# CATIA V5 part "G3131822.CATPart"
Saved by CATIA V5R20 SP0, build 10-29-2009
Part number: G3131822
Revision: 8
Definition: design
Nomenclature: G3131822
Source: made
Description: NOT SPECIFIED
Bounding box of the stored display mesh (mm): x -17 to 22, y -15.5 to 15.5, z -15.5 to 15.5
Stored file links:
  C:\Users\Raffaele\Desktop\3D X SITO CF\BOLEX\24-BUSH REF 313\G3131822.CATPart
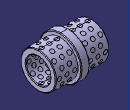
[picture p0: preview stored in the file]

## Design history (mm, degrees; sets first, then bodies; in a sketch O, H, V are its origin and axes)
Body1 "MANIFOLD_SOLID_BREP #11295" (main body)
  Solid1: solid without history
Body2 "MANIFOLD_SOLID_BREP #11438"
  Solid2: solid without history
Body3 "MANIFOLD_SOLID_BREP #11581"
  Solid3: solid without history
Body4 "MANIFOLD_SOLID_BREP #11724"
  Solid4: solid without history
Body5 "MANIFOLD_SOLID_BREP #11867"
  Solid5: solid without history
Body6 "MANIFOLD_SOLID_BREP #12012"
  Solid6: solid without history
Body7 "MANIFOLD_SOLID_BREP #12157"
  Solid7: solid without history
Body8 "MANIFOLD_SOLID_BREP #12302"
  Solid8: solid without history
Body9 "MANIFOLD_SOLID_BREP #12447"
  Solid9: solid without history
Body10 "MANIFOLD_SOLID_BREP #12592"
  Solid10: solid without history
Body11 "MANIFOLD_SOLID_BREP #12737"
  Solid11: solid without history
Body12 "MANIFOLD_SOLID_BREP #12882"
  Solid12: solid without history
Body13 "MANIFOLD_SOLID_BREP #13027"
  Solid13: solid without history
Body14 "MANIFOLD_SOLID_BREP #13172"
  Solid14: solid without history
Body15 "MANIFOLD_SOLID_BREP #13317"
  Solid15: solid without history
Body16 "MANIFOLD_SOLID_BREP #13462"
  Solid16: solid without history
Body17 "MANIFOLD_SOLID_BREP #13607"
  Solid17: solid without history
Body18 "MANIFOLD_SOLID_BREP #13754"
  Solid18: solid without history
Body19 "MANIFOLD_SOLID_BREP #13901"
  Solid19: solid without history
Body20 "MANIFOLD_SOLID_BREP #14048"
  Solid20: solid without history
Body21 "MANIFOLD_SOLID_BREP #14195"
  Solid21: solid without history
Body22 "MANIFOLD_SOLID_BREP #14340"
  Solid22: solid without history
Body23 "MANIFOLD_SOLID_BREP #14487"
  Solid23: solid without history
Body24 "MANIFOLD_SOLID_BREP #14634"
  Solid24: solid without history
Body25 "MANIFOLD_SOLID_BREP #14779"
  Solid25: solid without history
Body26 "MANIFOLD_SOLID_BREP #14924"
  Solid26: solid without history
Body27 "MANIFOLD_SOLID_BREP #15069"
  Solid27: solid without history
Body28 "MANIFOLD_SOLID_BREP #15214"
  Solid28: solid without history
Body29 "MANIFOLD_SOLID_BREP #15359"
  Solid29: solid without history
Body30 "MANIFOLD_SOLID_BREP #15504"
  Solid30: solid without history
Body31 "MANIFOLD_SOLID_BREP #15649"
  Solid31: solid without history
Body32 "MANIFOLD_SOLID_BREP #15792"
  Solid32: solid without history
Body33 "MANIFOLD_SOLID_BREP #15935"
  Solid33: solid without history
Body34 "MANIFOLD_SOLID_BREP #16082"
  Solid34: solid without history
Body35 "MANIFOLD_SOLID_BREP #16229"
  Solid35: solid without history
Body36 "MANIFOLD_SOLID_BREP #16376"
  Solid36: solid without history
Body37 "MANIFOLD_SOLID_BREP #16523"
  Solid37: solid without history
Body38 "MANIFOLD_SOLID_BREP #16668"
  Solid38: solid without history
Body39 "MANIFOLD_SOLID_BREP #16815"
  Solid39: solid without history
Body40 "MANIFOLD_SOLID_BREP #16962"
  Solid40: solid without history
Body41 "MANIFOLD_SOLID_BREP #17107"
  Solid41: solid without history
Body42 "MANIFOLD_SOLID_BREP #17252"
  Solid42: solid without history
Body43 "MANIFOLD_SOLID_BREP #17397"
  Solid43: solid without history
Body44 "MANIFOLD_SOLID_BREP #17542"
  Solid44: solid without history
Body45 "MANIFOLD_SOLID_BREP #17687"
  Solid45: solid without history
Body46 "MANIFOLD_SOLID_BREP #17832"
  Solid46: solid without history
Body47 "MANIFOLD_SOLID_BREP #17977"
  Solid47: solid without history
Body48 "MANIFOLD_SOLID_BREP #18122"
  Solid48: solid without history
Body49 "MANIFOLD_SOLID_BREP #18267"
  Solid49: solid without history
Body50 "MANIFOLD_SOLID_BREP #18412"
  Solid50: solid without history
Body51 "MANIFOLD_SOLID_BREP #18557"
  Solid51: solid without history
Body52 "MANIFOLD_SOLID_BREP #18702"
  Solid52: solid without history
Body53 "MANIFOLD_SOLID_BREP #18847"
  Solid53: solid without history
Body54 "MANIFOLD_SOLID_BREP #18992"
  Solid54: solid without history
Body55 "MANIFOLD_SOLID_BREP #19137"
  Solid55: solid without history
Body56 "MANIFOLD_SOLID_BREP #19282"
  Solid56: solid without history
Body57 "MANIFOLD_SOLID_BREP #19427"
  Solid57: solid without history
Body58 "MANIFOLD_SOLID_BREP #19572"
  Solid58: solid without history
Body59 "MANIFOLD_SOLID_BREP #19717"
  Solid59: solid without history
Body60 "MANIFOLD_SOLID_BREP #19860"
  Solid60: solid without history
Body61 "MANIFOLD_SOLID_BREP #20003"
  Solid61: solid without history
Body62 "MANIFOLD_SOLID_BREP #20146"
  Solid62: solid without history
Body63 "MANIFOLD_SOLID_BREP #20289"
  Solid63: solid without history
Body64 "MANIFOLD_SOLID_BREP #20432"
  Solid64: solid without history
Body65 "MANIFOLD_SOLID_BREP #20575"
  Solid65: solid without history
Body66 "MANIFOLD_SOLID_BREP #20722"
  Solid66: solid without history
Body67 "MANIFOLD_SOLID_BREP #20869"
  Solid67: solid without history
Body68 "MANIFOLD_SOLID_BREP #21016"
  Solid68: solid without history
Body69 "MANIFOLD_SOLID_BREP #21163"
  Solid69: solid without history
Body70 "MANIFOLD_SOLID_BREP #21310"
  Solid70: solid without history
Body71 "MANIFOLD_SOLID_BREP #21457"
  Solid71: solid without history
Body72 "MANIFOLD_SOLID_BREP #21604"
  Solid72: solid without history
Body73 "MANIFOLD_SOLID_BREP #21751"
  Solid73: solid without history
Body74 "MANIFOLD_SOLID_BREP #21896"
  Solid74: solid without history
Body75 "MANIFOLD_SOLID_BREP #22041"
  Solid75: solid without history
Body76 "MANIFOLD_SOLID_BREP #22188"
  Solid76: solid without history
Body77 "MANIFOLD_SOLID_BREP #22335"
  Solid77: solid without history
Body78 "MANIFOLD_SOLID_BREP #22482"
  Solid78: solid without history
Body79 "MANIFOLD_SOLID_BREP #22629"
  Solid79: solid without history
Body80 "MANIFOLD_SOLID_BREP #22774"
  Solid80: solid without history
Body81 "MANIFOLD_SOLID_BREP #22919"
  Solid81: solid without history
